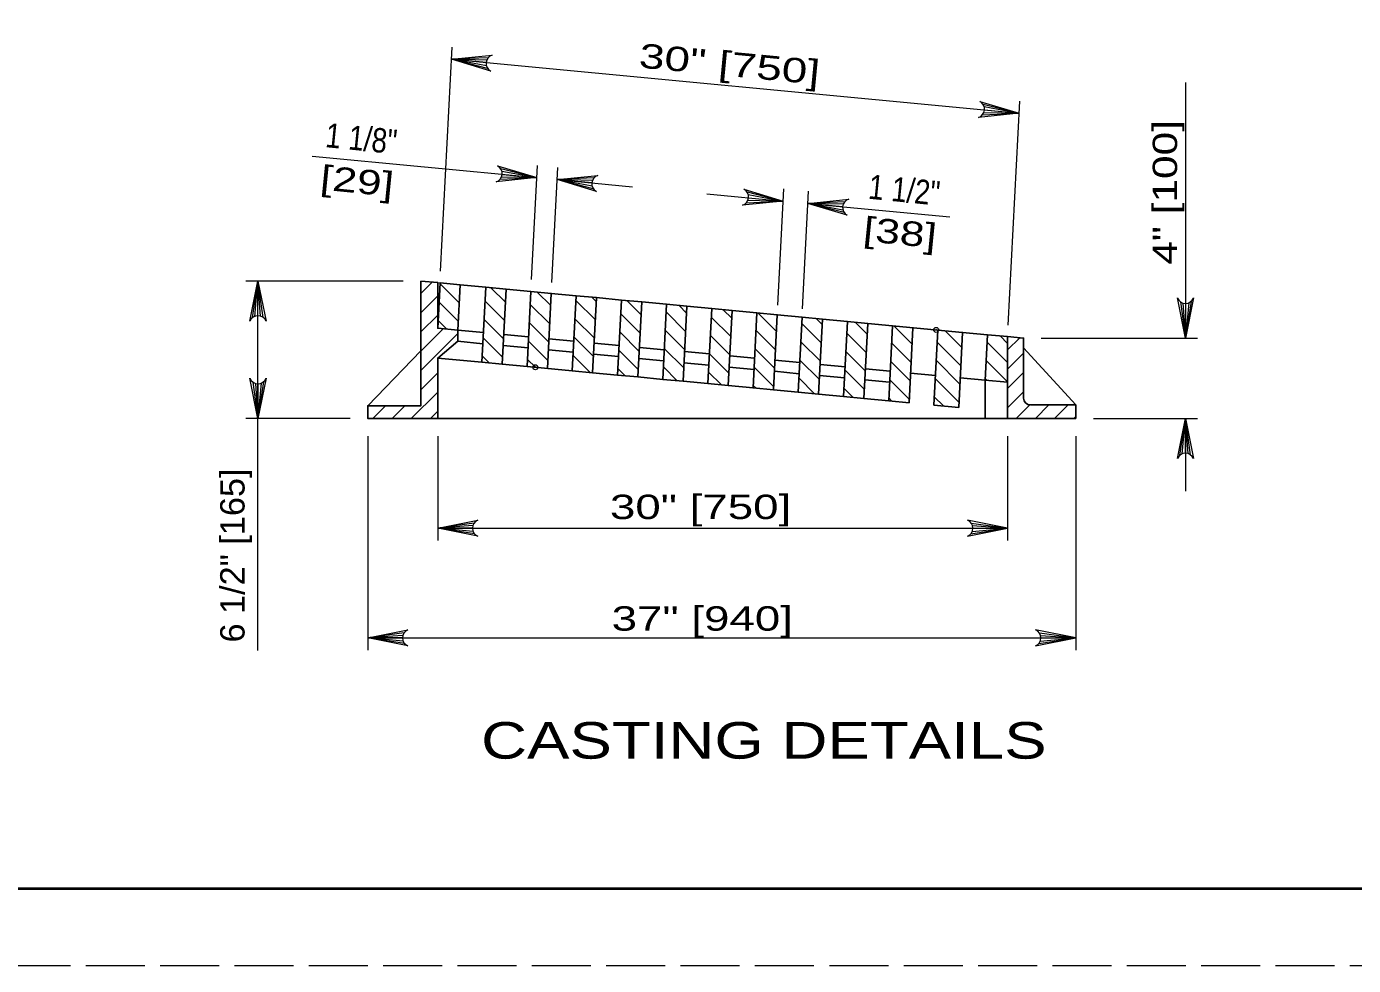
# Model space of a CAD drawing. Extents: x -1431.2 to -1397.2, y -1045.1 to -1001.1.
# Drawn here: x -1410.82 to -1402.18, y -1045.08 to -1038.97 of the extents above; entities that cross this region are included whole.
import ezdxf
from ezdxf.enums import TextEntityAlignment as Align

# ---------------------------------------------------------------- set-up
doc = ezdxf.new("R2010")
doc.units = 0
doc.header["$LTSCALE"] = 0.064
doc.header["$PDMODE"] = 32
doc.header["$PDSIZE"] = 0.032
doc.linetypes.add('LONG_DASHED', pattern=[7.5, 6, -1.5])
doc.layers.add('1', color=7, linetype='Continuous', lineweight=13)

msp = doc.modelspace()

# ---------------------------------------------------------------- linework, layer by layer
at = {"layer": '1'}
for p, q in [((-1408.12408, -1040.55958), (-1408.04917, -1039.10058)), ((-1407.81442, -1039.16933), (-1408.05325, -1039.17992)), ((-1407.828, -1039.20133), (-1408.05325, -1039.17992)), ((-1407.82583, -1039.22292), (-1408.05325, -1039.17992)), ((-1407.81825, -1039.23908), (-1408.05325, -1039.17992)), ((-1407.824, -1039.18492), (-1408.05325, -1039.17992)), ((-1408.05325, -1039.17992), (-1404.35833, -1039.53117)), ((-1403.2755, -1039.33175), (-1403.2755, -1040.99542)), ((-1404.59342, -1039.472), (-1404.35833, -1039.53117)), ((-1404.58583, -1039.48817), (-1404.35833, -1039.53117)), ((-1404.42925, -1040.9115), (-1404.35433, -1039.45175)), ((-1404.59717, -1039.54167), (-1404.35833, -1039.53117)), ((-1404.58767, -1039.52617), (-1404.35833, -1039.53117)), ((-1404.58367, -1039.50975), (-1404.35833, -1039.53117)), ((-1408.95975, -1039.81142), (-1407.49833, -1039.95033)), ((-1407.73333, -1039.89125), (-1407.49833, -1039.95033)), ((-1407.72575, -1039.90742), (-1407.49833, -1039.95033)), ((-1407.53225, -1040.61408), (-1407.49425, -1039.871)), ((-1407.40008, -1040.63292), (-1407.36158, -1039.88358)), ((-1407.73717, -1039.96092), (-1407.49833, -1039.95033)), ((-1407.72758, -1039.94542), (-1407.49833, -1039.95033)), ((-1407.72358, -1039.92892), (-1407.49833, -1039.95033)), ((-1407.12683, -1039.95242), (-1407.36567, -1039.963)), ((-1407.14042, -1039.98442), (-1407.36567, -1039.963)), ((-1407.13825, -1040.00592), (-1407.36567, -1039.963)), ((-1407.13067, -1040.02208), (-1407.36567, -1039.963)), ((-1407.13642, -1039.96792), (-1407.36567, -1039.963)), ((-1407.36567, -1039.963), (-1406.875, -1040.00958)), ((-1406.392, -1040.0555), (-1405.8945, -1040.10283)), ((-1406.1295, -1040.04367), (-1405.8945, -1040.10283)), ((-1406.12192, -1040.05983), (-1405.8945, -1040.10283)), ((-1406.11975, -1040.08142), (-1405.8945, -1040.10283)), ((-1405.92933, -1040.78167), (-1405.89042, -1040.02342)), ((-1405.76792, -1040.80375), (-1405.72875, -1040.03883)), ((-1406.13333, -1040.11333), (-1405.8945, -1040.10283)), ((-1406.12375, -1040.09783), (-1405.8945, -1040.10283)), ((-1405.494, -1040.10758), (-1405.73275, -1040.11817)), ((-1405.5075, -1040.13958), (-1405.73275, -1040.11817)), ((-1405.50533, -1040.16117), (-1405.73275, -1040.11817)), ((-1405.49775, -1040.17725), (-1405.73275, -1040.11817)), ((-1405.5035, -1040.12317), (-1405.73275, -1040.11817)), ((-1405.73275, -1040.11817), (-1404.81017, -1040.20583)), ((-1408.36833, -1040.62342), (-1409.3925, -1040.62342)), ((-1409.34975, -1040.863), (-1409.31317, -1040.62342)), ((-1409.33442, -1040.85392), (-1409.31317, -1040.62342)), ((-1409.31317, -1040.84975), (-1409.31317, -1040.62342)), ((-1409.29642, -1040.85217), (-1409.31317, -1040.62342)), ((-1409.28, -1040.86017), (-1409.31317, -1040.62342)), ((-1409.31317, -1043.02875), (-1409.31317, -1040.62342)), ((-1408.25292, -1040.7045), (-1408.17883, -1040.63042)), ((-1408.14308, -1040.63375), (-1408.128, -1040.63525)), ((-1408.00392, -1040.76533), (-1408.12825, -1040.64108)), ((-1407.70242, -1040.76125), (-1407.79708, -1040.66667)), ((-1407.40783, -1040.78325), (-1407.49592, -1040.69517)), ((-1408.25292, -1040.82983), (-1408.14308, -1040.72)), ((-1408.01008, -1040.88458), (-1408.13442, -1040.76017)), ((-1407.7085, -1040.88033), (-1407.83508, -1040.75383)), ((-1407.414, -1040.9025), (-1407.5405, -1040.77592)), ((-1407.11692, -1040.87658), (-1407.2435, -1040.75008)), ((-1407.11092, -1040.75742), (-1407.13942, -1040.72892)), ((-1406.81958, -1040.843), (-1406.91217, -1040.75042)), ((-1406.52325, -1040.83175), (-1406.57233, -1040.78267)), ((-1403.30858, -1040.75867), (-1403.2755, -1040.99542)), ((-1403.29217, -1040.76667), (-1403.2755, -1040.99542)), ((-1403.23883, -1040.75592), (-1403.2755, -1040.99542)), ((-1403.25417, -1040.76492), (-1403.2755, -1040.99542)), ((-1403.2755, -1040.76917), (-1403.2755, -1040.99542)), ((-1408.25292, -1040.95508), (-1408.14308, -1040.84533)), ((-1407.71458, -1040.99958), (-1407.84108, -1040.87308)), ((-1407.12308, -1040.99583), (-1407.24967, -1040.86917)), ((-1406.82575, -1040.96217), (-1406.95225, -1040.83567)), ((-1406.52942, -1040.951), (-1406.656, -1040.82442)), ((-1406.2355, -1040.985), (-1406.36208, -1040.85833)), ((-1406.22942, -1040.86575), (-1406.28517, -1040.81)), ((-1405.93825, -1040.953), (-1406.05983, -1040.83142)), ((-1405.64017, -1040.90667), (-1405.67942, -1040.86742)), ((-1408.25292, -1041.08042), (-1408.10683, -1040.93442)), ((-1408.08333, -1040.93658), (-1408.1405, -1040.87942)), ((-1407.42017, -1041.02167), (-1407.54667, -1040.89517)), ((-1406.83175, -1041.08133), (-1406.95842, -1040.95483)), ((-1406.53558, -1041.07008), (-1406.66208, -1040.94358)), ((-1405.94425, -1041.07217), (-1406.07092, -1040.94558)), ((-1405.64633, -1041.02592), (-1405.77283, -1040.89942)), ((-1405.34775, -1040.97017), (-1405.42642, -1040.89158)), ((-1405.05542, -1041.03483), (-1405.17483, -1040.91533)), ((-1405.03642, -1040.9285), (-1405.03642, -1040.92833)), ((-1404.73125, -1041.05608), (-1404.84025, -1040.94708)), ((-1408.25292, -1041.20567), (-1408.01308, -1040.96592)), ((-1407.72075, -1041.11875), (-1407.84725, -1040.99225)), ((-1407.42617, -1041.14075), (-1407.55283, -1041.01425)), ((-1407.12925, -1041.11492), (-1407.25575, -1040.98842)), ((-1406.24167, -1041.10408), (-1406.36817, -1040.97758)), ((-1405.65233, -1041.14508), (-1405.779, -1041.01858)), ((-1405.35383, -1041.08942), (-1405.48042, -1040.96283)), ((-1405.0615, -1041.15392), (-1405.188, -1041.02742)), ((-1404.73742, -1041.17517), (-1404.89208, -1041.0205)), ((-1404.43308, -1041.1545), (-1404.56683, -1041.02075)), ((-1404.43308, -1041.02917), (-1404.48117, -1040.981)), ((-1404.43308, -1041.07217), (-1404.35408, -1040.99308)), ((-1404.21417, -1040.99542), (-1403.19608, -1040.99542)), ((-1407.80842, -1041.15633), (-1407.85342, -1041.11133)), ((-1407.15075, -1041.21875), (-1407.26192, -1041.1075)), ((-1406.83792, -1041.2005), (-1406.96442, -1041.07392)), ((-1406.54175, -1041.18925), (-1406.66825, -1041.06275)), ((-1406.24775, -1041.22333), (-1406.37433, -1041.09667)), ((-1405.95042, -1041.19133), (-1406.077, -1041.06483)), ((-1405.35992, -1041.2085), (-1405.48658, -1041.08208)), ((-1404.43308, -1041.1975), (-1404.32958, -1041.094)), ((-1407.72308, -1041.1645), (-1407.72308, -1041.16458)), ((-1407.50742, -1041.18492), (-1407.55892, -1041.1335)), ((-1407.50742, -1041.185), (-1407.50742, -1041.18492)), ((-1407.26708, -1041.20767), (-1407.26708, -1041.20783)), ((-1406.92342, -1041.24025), (-1406.97058, -1041.19317)), ((-1406.58367, -1041.2725), (-1406.67442, -1041.182)), ((-1406.29658, -1041.29983), (-1406.38042, -1041.21592)), ((-1405.95658, -1041.31042), (-1406.08308, -1041.18392)), ((-1405.6585, -1041.26425), (-1405.785, -1041.13767)), ((-1405.36608, -1041.32775), (-1405.49258, -1041.20117)), ((-1405.06758, -1041.27317), (-1405.19417, -1041.1465)), ((-1404.7435, -1041.29442), (-1404.89808, -1041.13975)), ((-1404.43308, -1041.27975), (-1404.57283, -1041.13992)), ((-1404.43308, -1041.32275), (-1404.32958, -1041.21925)), ((-1409.34625, -1041.28167), (-1409.31317, -1041.51842)), ((-1409.32992, -1041.28967), (-1409.31317, -1041.51842)), ((-1409.2765, -1041.27883), (-1409.31317, -1041.51842)), ((-1409.29192, -1041.28792), (-1409.31317, -1041.51842)), ((-1409.31317, -1041.29208), (-1409.31317, -1041.51842)), ((-1408.25292, -1041.331), (-1408.14308, -1041.22125)), ((-1406.97283, -1041.23558), (-1406.97283, -1041.23575)), ((-1406.07117, -1041.32125), (-1406.08925, -1041.30317)), ((-1405.69075, -1041.35733), (-1405.79117, -1041.25692)), ((-1405.07375, -1041.39225), (-1405.20033, -1041.26575)), ((-1404.74958, -1041.41358), (-1404.90425, -1041.25883)), ((-1404.56817, -1041.26992), (-1404.579, -1041.25908)), ((-1408.315, -1041.51842), (-1408.14308, -1041.3465)), ((-1405.438, -1041.38117), (-1405.49875, -1041.32042)), ((-1405.18617, -1041.40508), (-1405.20642, -1041.38483)), ((-1404.85167, -1041.43675), (-1404.91042, -1041.37808)), ((-1404.43308, -1041.448), (-1404.32958, -1041.3445)), ((-1408.56558, -1041.51842), (-1408.48225, -1041.43508)), ((-1408.44033, -1041.51842), (-1408.357, -1041.43508)), ((-1408.18967, -1041.51842), (-1408.14308, -1041.47183)), ((-1404.37817, -1041.51842), (-1404.28883, -1041.42917)), ((-1404.25275, -1041.51842), (-1404.16417, -1041.42975)), ((-1404.1275, -1041.51842), (-1404.03892, -1041.42975)), ((-1408.71417, -1041.51842), (-1409.3925, -1041.51842)), ((-1404.00225, -1041.51842), (-1403.98992, -1041.50608)), ((-1403.8745, -1041.51842), (-1403.19608, -1041.51842)), ((-1403.63167, -1041.51825), (-1403.63167, -1041.51842)), ((-1403.31208, -1041.75792), (-1403.2755, -1041.51842)), ((-1403.29675, -1041.74883), (-1403.2755, -1041.51842)), ((-1403.2755, -1041.74467), (-1403.2755, -1041.51842)), ((-1403.25875, -1041.74708), (-1403.2755, -1041.51842)), ((-1403.24233, -1041.75517), (-1403.2755, -1041.51842)), ((-1403.2755, -1041.51842), (-1403.2755, -1041.99267)), ((-1408.59867, -1041.63383), (-1408.59867, -1043.02667)), ((-1408.14308, -1041.63383), (-1408.14308, -1042.31225)), ((-1404.43308, -1041.63383), (-1404.43308, -1042.31225)), ((-1403.98992, -1041.63383), (-1403.98992, -1043.02667)), ((-1407.90633, -1042.19967), (-1408.14308, -1042.23283)), ((-1407.91442, -1042.21608), (-1408.14308, -1042.23283)), ((-1407.91683, -1042.23283), (-1408.14308, -1042.23283)), ((-1407.91267, -1042.25408), (-1408.14308, -1042.23283)), ((-1407.90358, -1042.26942), (-1408.14308, -1042.23283)), ((-1408.14308, -1042.23283), (-1404.43308, -1042.23283)), ((-1404.67258, -1042.26942), (-1404.43308, -1042.23283)), ((-1404.66983, -1042.19967), (-1404.43308, -1042.23283)), ((-1404.6635, -1042.25408), (-1404.43308, -1042.23283)), ((-1404.66175, -1042.21608), (-1404.43308, -1042.23283)), ((-1404.65933, -1042.23283), (-1404.43308, -1042.23283)), ((-1408.36192, -1042.91417), (-1408.59867, -1042.94725)), ((-1408.37, -1042.93058), (-1408.59867, -1042.94725)), ((-1408.37242, -1042.94725), (-1408.59867, -1042.94725)), ((-1408.36825, -1042.96858), (-1408.59867, -1042.94725)), ((-1408.35917, -1042.98392), (-1408.59867, -1042.94725)), ((-1408.59867, -1042.94725), (-1403.98992, -1042.94725)), ((-1404.22942, -1042.98392), (-1403.98992, -1042.94725)), ((-1404.22667, -1042.91417), (-1403.98992, -1042.94725)), ((-1404.22042, -1042.96858), (-1403.98992, -1042.94725)), ((-1404.21867, -1042.93058), (-1403.98992, -1042.94725)), ((-1404.21617, -1042.94725), (-1403.98992, -1042.94725))]:
    msp.add_line(p, q, dxfattribs=at)
at = {"layer": '1', "lineweight": 25}
for p, q in [((-1408.25292, -1040.62342), (-1408.14308, -1040.63375)), ((-1408.14308, -1040.93092), (-1408.128, -1040.63525)), ((-1408.128, -1040.63525), (-1407.99792, -1040.64758)), ((-1407.99792, -1040.64758), (-1408.01308, -1040.94325)), ((-1407.99792, -1040.64758), (-1407.83042, -1040.66342)), ((-1407.83042, -1040.66358), (-1407.8555, -1041.15208)), ((-1407.698, -1040.676), (-1407.83042, -1040.66342)), ((-1407.72308, -1041.16458), (-1407.698, -1040.67608)), ((-1407.698, -1040.676), (-1407.53617, -1040.69133)), ((-1407.40375, -1040.70392), (-1407.24192, -1040.71917)), ((-1407.26708, -1041.20783), (-1407.24192, -1040.71933)), ((-1407.24192, -1040.71917), (-1407.1095, -1040.73175)), ((-1407.1095, -1040.73183), (-1407.13467, -1041.22033)), ((-1407.1095, -1040.73175), (-1406.94767, -1040.74708)), ((-1406.97283, -1041.23575), (-1406.94767, -1040.74725)), ((-1406.94767, -1040.74708), (-1406.81525, -1040.75967)), ((-1406.81525, -1040.75975), (-1406.84042, -1041.24825)), ((-1406.81525, -1040.75967), (-1406.65342, -1040.775)), ((-1406.52108, -1040.78758), (-1406.35925, -1040.803)), ((-1406.22683, -1040.8155), (-1406.065, -1040.83092)), ((-1405.93258, -1040.84342), (-1405.77075, -1040.85883)), ((-1405.63833, -1040.87142), (-1405.4765, -1040.88675)), ((-1408.01308, -1040.94325), (-1407.84567, -1040.95908)), ((-1405.4765, -1040.88675), (-1405.34408, -1040.89933)), ((-1405.34408, -1040.89933), (-1405.18225, -1040.91458)), ((-1404.72617, -1040.95775), (-1404.56433, -1040.97317)), ((-1408.01308, -1041.016), (-1407.84933, -1041.0315)), ((-1407.717, -1041.044), (-1407.55517, -1041.05925)), ((-1407.71317, -1040.97167), (-1407.55133, -1040.98692)), ((-1407.41892, -1040.9995), (-1407.25708, -1041.01475)), ((-1407.12467, -1041.02742), (-1406.96283, -1041.04267)), ((-1404.43308, -1041.51842), (-1404.43308, -1040.98558)), ((-1408.59867, -1041.43508), (-1408.25292, -1041.07825)), ((-1408.14308, -1041.12475), (-1407.8555, -1041.15192)), ((-1407.42275, -1041.07192), (-1407.26092, -1041.08733)), ((-1407.1285, -1041.09975), (-1406.96667, -1041.11517)), ((-1406.83425, -1041.12767), (-1406.67242, -1041.14308)), ((-1406.83042, -1041.05525), (-1406.66858, -1041.0705)), ((-1406.53633, -1041.08317), (-1406.37433, -1041.0985)), ((-1406.24192, -1041.11108), (-1406.08008, -1041.1265)), ((-1403.98992, -1041.42975), (-1404.32958, -1041.05925)), ((-1407.8555, -1041.15192), (-1407.72308, -1041.1645)), ((-1407.72308, -1041.1645), (-1407.56125, -1041.17983)), ((-1407.13467, -1041.22025), (-1407.26708, -1041.20767)), ((-1406.54, -1041.15558), (-1406.37817, -1041.17092)), ((-1406.24575, -1041.18342), (-1406.08392, -1041.19867)), ((-1405.9515, -1041.21133), (-1405.78967, -1041.22675)), ((-1405.94767, -1041.139), (-1405.78583, -1041.15442)), ((-1405.65342, -1041.16692), (-1405.49167, -1041.18233)), ((-1405.35933, -1041.19492), (-1405.19742, -1041.21025)), ((-1407.13467, -1041.22025), (-1406.97283, -1041.23558)), ((-1406.84042, -1041.24817), (-1406.97283, -1041.23558)), ((-1406.54617, -1041.27608), (-1406.38433, -1041.2915)), ((-1406.25192, -1041.304), (-1406.09008, -1041.31942)), ((-1405.65725, -1041.23933), (-1405.49542, -1041.25467)), ((-1405.363, -1041.26708), (-1405.20117, -1041.2825)), ((-1405.065, -1041.22283), (-1404.90317, -1041.23817)), ((-1404.74133, -1041.25342), (-1404.5795, -1041.26883)), ((-1404.5795, -1041.51842), (-1404.5795, -1041.26883)), ((-1405.95767, -1041.332), (-1405.79583, -1041.34733)), ((-1405.66342, -1041.35992), (-1405.79583, -1041.34733)), ((-1405.36917, -1041.38767), (-1405.20733, -1041.40308)), ((-1408.14308, -1041.51842), (-1404.43308, -1041.51842))]:
    msp.add_line(p, q, dxfattribs=at)
at = {"layer": '1', "linetype": 'LONG_DASHED'}
msp.add_lwpolyline([(-1431.24575, -1045.07983), (-1397.24575, -1045.07983), (-1397.24575, -1023.07983), (-1431.24575, -1023.07983)], close=True, dxfattribs=at)
at = {"layer": '1', "lineweight": 25}
for points in [[(-1397.74575, -1044.57983), (-1429.24575, -1044.57983), (-1429.24575, -1023.57983)], [(-1408.01308, -1041.016), (-1408.14308, -1041.12475), (-1408.14308, -1041.51842), (-1408.59867, -1041.51842), (-1408.59867, -1041.43508), (-1408.25292, -1041.43508), (-1408.25292, -1040.62342)], [(-1408.14308, -1040.63392), (-1408.14308, -1040.93092), (-1408.01308, -1040.94325), (-1408.01308, -1041.01833)], [(-1407.56125, -1041.17983), (-1407.53617, -1040.69133), (-1407.40375, -1040.70392), (-1407.42883, -1041.19242)], [(-1406.84042, -1041.24817), (-1406.67858, -1041.26358), (-1406.65342, -1040.775), (-1406.52108, -1040.78758), (-1406.54617, -1041.27608), (-1406.67858, -1041.26358)], [(-1405.79583, -1041.34733), (-1405.77075, -1040.85883), (-1405.63833, -1040.87142), (-1405.66342, -1041.35975)], [(-1405.66342, -1041.35992), (-1405.50158, -1041.37517), (-1405.4765, -1040.88667)], [(-1405.34408, -1040.89917), (-1405.36917, -1041.38767), (-1405.50158, -1041.37517)], [(-1405.20733, -1041.40308), (-1405.18225, -1040.91458), (-1404.888, -1040.9425)], [(-1405.04983, -1040.92717), (-1405.07492, -1041.41567), (-1405.20733, -1041.40308)], [(-1404.43308, -1040.98558), (-1404.56433, -1040.97317), (-1404.5795, -1041.26883), (-1404.43308, -1041.28275)], [(-1404.43308, -1040.98558), (-1404.32958, -1040.99542), (-1404.32958, -1041.3855)], [(-1407.56125, -1041.17983), (-1407.26708, -1041.20767), (-1407.56125, -1041.17983)], [(-1404.28525, -1041.42975), (-1403.98992, -1041.42975), (-1403.98992, -1041.51842), (-1404.43308, -1041.51842)]]:
    msp.add_lwpolyline(points, dxfattribs=at)
at = {"layer": '1', "lineweight": 40}
msp.add_lwpolyline([(-1429.24575, -1023.57983), (-1397.74575, -1023.57983), (-1397.74575, -1044.57983), (-1429.24575, -1044.57983)], close=True, dxfattribs=at)
at = {"layer": '1'}
for points in [[(-1407.79792, -1039.25675), (-1408.05325, -1039.17992), (-1407.788, -1039.15258)], [(-1404.61375, -1039.45433), (-1404.35833, -1039.53117), (-1404.62367, -1039.55842)], [(-1407.75367, -1039.87358), (-1407.49833, -1039.95033), (-1407.76358, -1039.97767)], [(-1407.11033, -1040.03975), (-1407.36567, -1039.963), (-1407.10042, -1039.93567)], [(-1406.14992, -1040.026), (-1405.8945, -1040.10283), (-1406.15975, -1040.13008)], [(-1405.47742, -1040.195), (-1405.73275, -1040.11817), (-1405.4675, -1040.09083)], [(-1409.36542, -1040.88492), (-1409.31317, -1040.62342), (-1409.26083, -1040.88492)], [(-1403.22317, -1040.73392), (-1403.2755, -1040.99542), (-1403.32775, -1040.73392)], [(-1409.26083, -1041.25683), (-1409.31317, -1041.51842), (-1409.36542, -1041.25683)], [(-1403.32775, -1041.77992), (-1403.2755, -1041.51842), (-1403.22317, -1041.77992)], [(-1407.88158, -1042.28517), (-1408.14308, -1042.23283), (-1407.88158, -1042.1805)], [(-1404.69458, -1042.28517), (-1404.43308, -1042.23283), (-1404.69458, -1042.1805)], [(-1408.33717, -1042.99958), (-1408.59867, -1042.94725), (-1408.33717, -1042.895)], [(-1404.25142, -1042.99958), (-1403.98992, -1042.94725), (-1404.25142, -1042.895)]]:
    msp.add_lwpolyline(points, dxfattribs=at)
at = {"layer": '1', "lineweight": 25}
for points in [[(-1406.38433, -1041.2915), (-1406.35925, -1040.803), (-1406.22683, -1040.8155), (-1406.25192, -1041.304)], [(-1405.95767, -1041.332), (-1405.93258, -1040.84342), (-1406.065, -1040.83092), (-1406.09008, -1041.31942)], [(-1404.91308, -1041.431), (-1404.888, -1040.9425), (-1404.72617, -1040.95775), (-1404.75125, -1041.44625)]]:
    msp.add_lwpolyline(points, close=True, dxfattribs=at)
at = {"layer": '1'}
for centre, start, end in [((-1407.77191, -1039.20662), 106.65835, 242.48447), ((-1404.63974, -1039.50444), 286.65835, 62.48447), ((-1407.77968, -1039.92367), 286.65835, 62.48447), ((-1407.08432, -1039.98965), 106.65835, 242.48447), ((-1406.17586, -1040.07611), 286.65835, 62.48447), ((-1405.45143, -1040.14484), 106.65835, 242.48447), ((-1403.27552, -1040.71279), 202.08782, 337.91395), ((-1409.31309, -1040.90607), 22.08782, 157.91395), ((-1409.31321, -1041.23575), 202.08782, 337.91395), ((-1403.2754, -1041.80101), 22.08782, 157.91395), ((-1407.8605, -1042.23277), 112.08782, 247.91395), ((-1404.71568, -1042.23277), 292.08605, 67.91218), ((-1408.31607, -1042.94723), 112.08782, 247.91395), ((-1404.27253, -1042.94723), 292.08605, 67.91218)]:
    msp.add_arc(centre, 0.05644, start, end, dxfattribs=at)
at = {"layer": '1', "lineweight": 25}
msp.add_ellipse((-1404.28525, -1041.38548), major_axis=(-0.0443, 0), ratio=0.999895, start_param=6.2831853, end_param=7.8539816, dxfattribs=at)
at = {"layer": '1'}
for p in [(-1404.898, -1040.9415), (-1407.50742, -1041.18492)]:
    msp.add_point(p, dxfattribs=at)

# ---------------------------------------------------------------- texts
for s, rotation, width, p in [('30" [750]', 354.57, 1.4, (-1406.83783, -1039.23308)), ('4" [100]', 90, 1.3, (-1403.32983, -1040.51742)), ('6 1/2" [165]', 90, 1.05, (-1409.40042, -1042.97692))]:
    msp.add_text(s, height=0.1588, rotation=rotation, dxfattribs=dict(at, width=width)).set_placement(p)
for s, width, p in [('1 1/8"', 0.85, (-1408.64795, -1039.77435)), ('[29]', 1.35, (-1408.67541, -1040.05073)), ('1 1/2"', 0.85, (-1405.11341, -1040.10993)), ('[38]', 1.35, (-1405.14099, -1040.38635))]:
    msp.add_text(s, height=0.1588, rotation=354.311, dxfattribs=dict(at, width=width)).set_placement(p, align=Align.CENTER)
for s, height, width, p in [('30" [750]', 0.1588, 1.4, (-1407.022, -1042.17333)), ('37" [940]', 0.1588, 1.4, (-1407.01083, -1042.9)), ('CASTING DETAILS', 0.2382, 1.3, (-1407.86075, -1043.73333))]:
    msp.add_text(s, height=height, dxfattribs=dict(at, width=width)).set_placement(p)

doc.saveas('drawing.dxf')
